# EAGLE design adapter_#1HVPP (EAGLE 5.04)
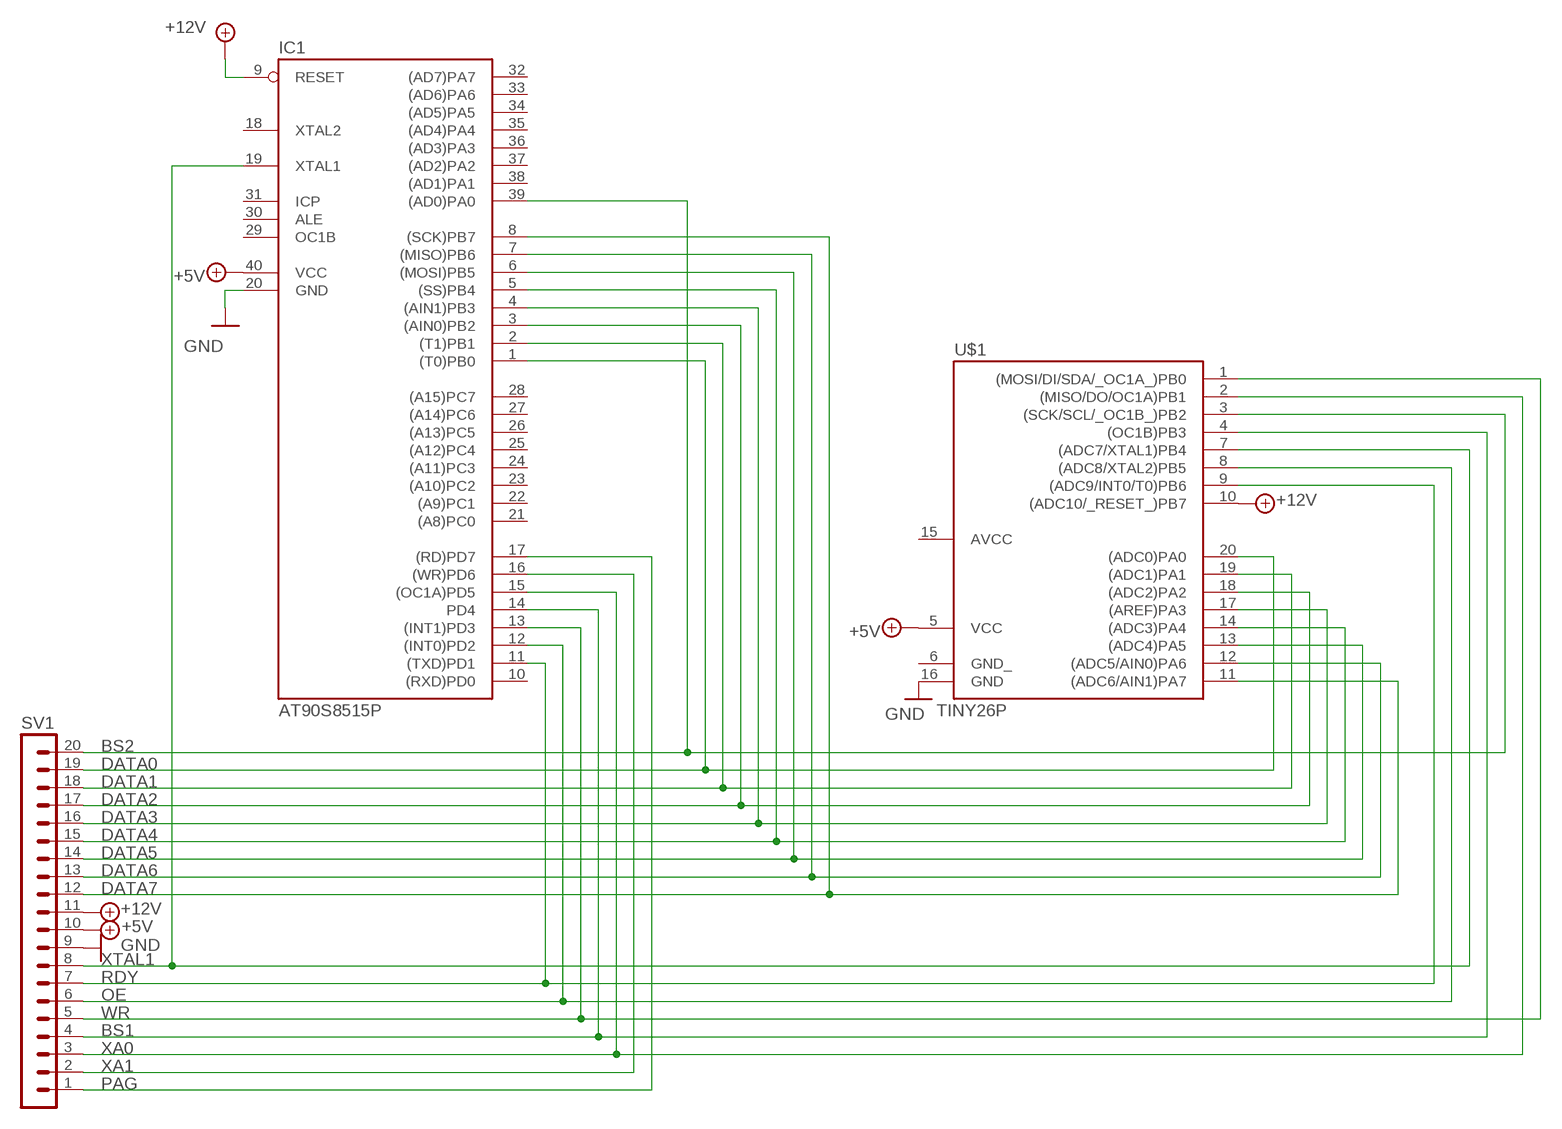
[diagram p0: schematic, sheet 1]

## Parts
IC1  AT90S8515P  [DIL40]
SV1  MA20-1  [MA20-1]
U$1  TINY26P  [DIL20]

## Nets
+5V: IC1.40(VCC) SV1.10 U$1.5(VCC)
+12V: IC1.9(RESET) SV1.11 U$1.10((ADC10/_RESET_)PB7)
BS1: IC1.14(PD4) SV1.4 U$1.4((OC1B)PB3)
BS2: IC1.39((AD0)PA0) SV1.20 U$1.3((SCK/SCL/_OC1B_)PB2)
DATA0: IC1.1((T0)PB0) SV1.19 U$1.20((ADC0)PA0)
DATA1: IC1.2((T1)PB1) SV1.18 U$1.19((ADC1)PA1)
DATA2: IC1.3((AIN0)PB2) SV1.17 U$1.18((ADC2)PA2)
DATA3: IC1.4((AIN1)PB3) SV1.16 U$1.17((AREF)PA3)
DATA4: IC1.5((SS)PB4) SV1.15 U$1.14((ADC3)PA4)
DATA5: IC1.6((MOSI)PB5) SV1.14 U$1.13((ADC4)PA5)
DATA6: IC1.7((MISO)PB6) SV1.13 U$1.12((ADC5/AIN0)PA6)
DATA7: IC1.8((SCK)PB7) SV1.12 U$1.11((ADC6/AIN1)PA7)
GND: IC1.20(GND) SV1.9 U$1.16(GND)
OE: IC1.12((INT0)PD2) SV1.6 U$1.8((ADC8/XTAL2)PB5)
PAG: IC1.17((RD)PD7) SV1.1
RDY: IC1.11((TXD)PD1) SV1.7 U$1.9((ADC9/INT0/T0)PB6)
WR: IC1.13((INT1)PD3) SV1.5 U$1.1((MOSI/DI/SDA/_OC1A_)PB0)
XA0: IC1.15((OC1A)PD5) SV1.3 U$1.2((MISO/DO/OC1A)PB1)
XA1: IC1.16((WR)PD6) SV1.2
XTAL1: IC1.19(XTAL1) SV1.8 U$1.7((ADC7/XTAL1)PB4)
Unconnected: IC1.10((RXD)PD0) IC1.18(XTAL2) IC1.21((A8)PC0) IC1.22((A9)PC1) IC1.23((A10)PC2) IC1.24((A11)PC3) IC1.25((A12)PC4) IC1.26((A13)PC5) IC1.27((A14)PC6) IC1.28((A15)PC7) IC1.29(OC1B) IC1.30(ALE) IC1.31(ICP) IC1.32((AD7)PA7) IC1.33((AD6)PA6) IC1.34((AD5)PA5) IC1.35((AD4)PA4) IC1.36((AD3)PA3) IC1.37((AD2)PA2) IC1.38((AD1)PA1)

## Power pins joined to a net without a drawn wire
AVCC: U$1.15(AVCC)
GND_: U$1.6(GND_)

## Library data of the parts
IC1 = avr-4:AT90S8515P: MICROCONTROLLER 8 Kbytes FLASH 512 bytes SRAM 512 bytes EEPROM UART
SV1 = con-lstb:MA20-1: PIN HEADER
U$1 = avr-4:TINY26

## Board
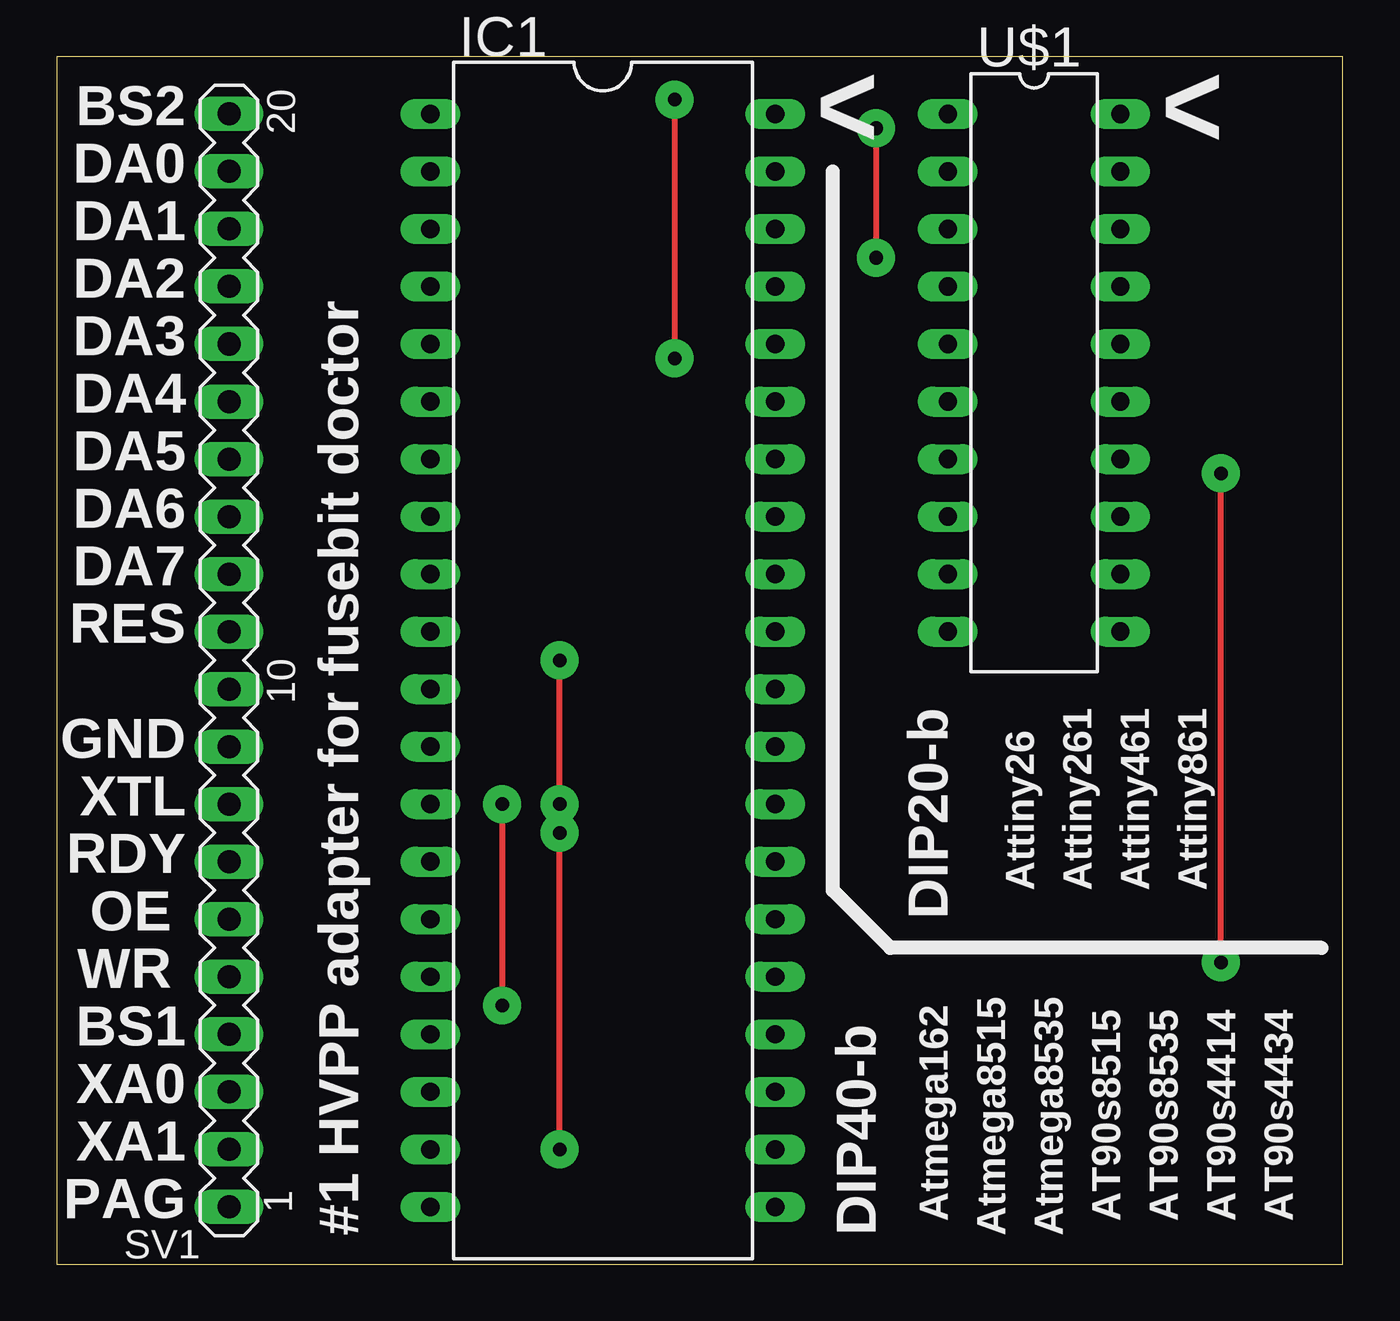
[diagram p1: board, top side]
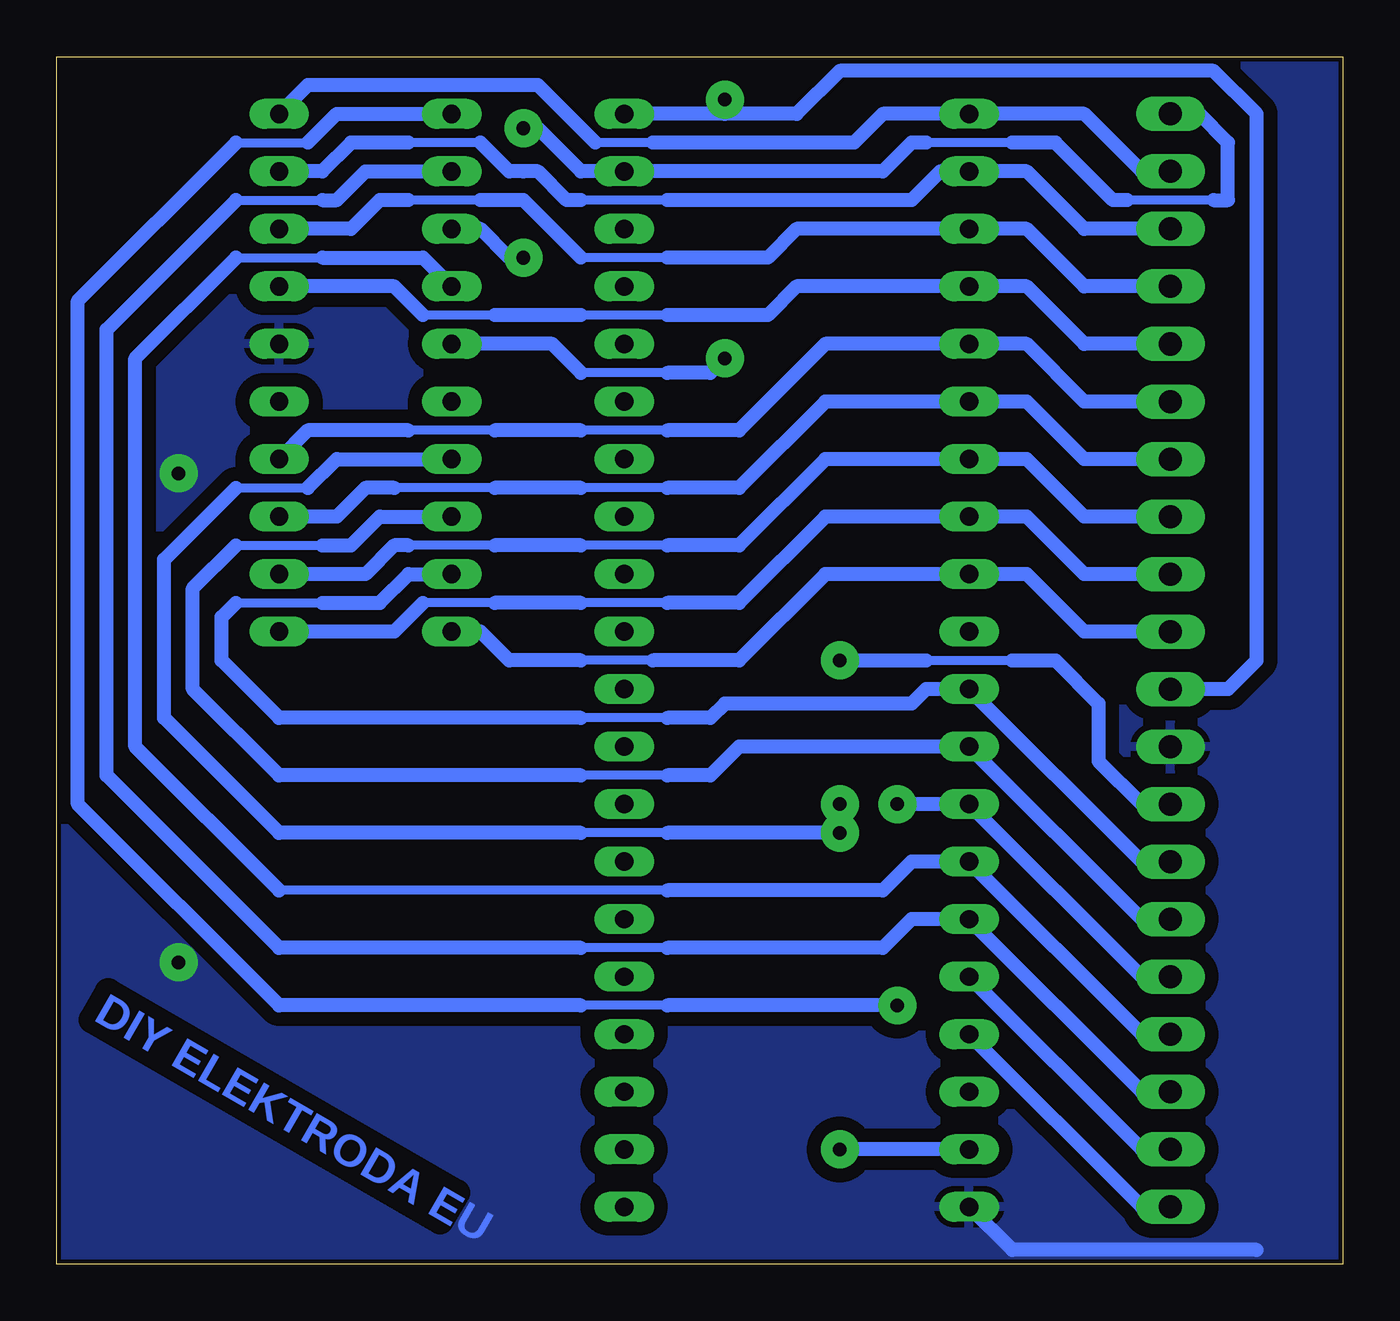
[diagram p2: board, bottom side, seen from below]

Size 56.82 x 53.33 mm. Coordinates in mm from the lower left corner, seen from the top.
Outline: 0,0 56.82,0 56.82,53.33 0,53.33 0,0
Copper layers (1*16): Top 0.035mm / dielectric 1.5mm / Bottom 0.035mm
Design rules "default *": minimum track width 10mil, minimum drill 24mil, track to track 24mil, track to pad 24mil, pad to pad 8mil, via to via 8mil, smd to smd 8mil, copper to edge 8mil, drill to drill 8mil, minimum pad ring 10mil, minimum via ring 8mil, stop-mask expansion 4mil, vias tented up to drill 0mil, thermal gap 10mil

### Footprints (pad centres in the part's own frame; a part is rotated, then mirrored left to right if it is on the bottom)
DIL40 = drill 0.813 long: 1 -24.13,-7.62; 2 -21.59,-7.62; 3 -19.05,-7.62; 4 -16.51,-7.62; 5 -13.97,-7.62; 6 -11.43,-7.62; 7 -8.89,-7.62; 8 -6.35,-7.62; 9 -3.81,-7.62; 10 -1.27,-7.62; 11 1.27,-7.62; 12 3.81,-7.62; 13 6.35,-7.62; 14 8.89,-7.62; 15 11.43,-7.62; 16 13.97,-7.62; 17 16.51,-7.62; 18 19.05,-7.62; 19 21.59,-7.62; 20 24.13,-7.62; 21 24.13,7.62; 22 21.59,7.62; 23 19.05,7.62; 24 16.51,7.62; 25 13.97,7.62; 26 11.43,7.62; 27 8.89,7.62; 28 6.35,7.62; 29 3.81,7.62; 30 1.27,7.62; 31 -1.27,7.62; 32 -3.81,7.62; 33 -6.35,7.62; 34 -8.89,7.62; 35 -11.43,7.62; 36 -13.97,7.62; 37 -16.51,7.62; 38 -19.05,7.62; 39 -21.59,7.62; 40 -24.13,7.62
MA20-1 = drill 1.016 long: 1 -24.13,0; 2 -21.59,0; 3 -19.05,0; 4 -16.51,0; 5 -13.97,0; 6 -11.43,0; 7 -8.89,0; 8 -6.35,0; 9 -3.81,0; 10 -1.27,0; 11 1.27,0; 12 3.81,0; 13 6.35,0; 14 8.89,0; 15 11.43,0; 16 13.97,0; 17 16.51,0; 18 19.05,0; 19 21.59,0; 20 24.13,0
DIL20 = drill 0.813 long: 1 -11.43,-3.81; 2 -8.89,-3.81; 3 -6.35,-3.81; 4 -3.81,-3.81; 5 -1.27,-3.81; 6 1.27,-3.81; 7 3.81,-3.81; 8 6.35,-3.81; 9 8.89,-3.81; 10 11.43,-3.81; 11 11.43,3.81; 12 8.89,3.81; 13 6.35,3.81; 14 3.81,3.81; 15 1.27,3.81; 16 -1.27,3.81; 17 -3.81,3.81; 18 -6.35,3.81; 19 -8.89,3.81; 20 -11.43,3.81

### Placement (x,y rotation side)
IC1  24.13,26.67 270 top
SV1  7.62,26.67 90 top
U$1  43.18,39.37 270 top

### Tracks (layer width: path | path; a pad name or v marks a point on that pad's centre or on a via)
+5V  (via drill 0.6 pad 1.68)
  Top 0.254: v27.3,51.44 v27.3,40.01
  Bottom 0.406: 29.84,39.37 33.66,39.37
  Bottom 0.61: SV1.10 5.08,25.4 3.81,26.67 3.81,50.8 5.71,52.7 22.23,52.7 24.13,50.8 27.3,50.8 | 27.3,50.8 IC1.40 | 27.3,50.8 v27.3,51.44 | U$1.5 34.92,40.64 33.66,39.37 | 29.84,39.37 27.94,39.37 v27.3,40.01
+12V
  Bottom 0.406: 30.48,26.67 33.66,26.67
  Bottom 0.61: SV1.11 11.43,27.94 13.97,30.48 IC1.9 22.86,30.48 26.67,26.67 30.48,26.67 | 33.66,26.67 36.83,26.67 38.1,27.94 U$1.10
BS1
  Bottom 0.406: 48.9,44.45 45.09,44.45 | 29.84,16.51 46.99,16.51
  Bottom 0.61: SV1.4 8.89,10.16 IC1.14 19.05,17.78 20.32,16.51 29.84,16.51 | U$1.4 40.64,44.45 45.09,44.45 | 48.9,44.45 53.34,40.01 53.34,22.86 46.99,16.51
BS2  (via drill 0.6 pad 1.68)
  Top 0.254: v36.2,50.16 v36.2,44.45
  Bottom 0.406: 5.71,46.99 9.53,46.99 | 14.61,49.53 18.41,49.53
  Bottom 0.61: SV1.20 6.35,50.8 5.08,49.53 5.08,46.99 5.71,46.99 | 9.53,46.99 10.16,46.99 12.7,49.53 14.61,49.53 | 18.41,49.53 19.05,49.53 20.32,48.26 IC1.39 33.66,48.26 35.56,50.16 v36.2,50.16 | U$1.3 38.1,45.72 36.83,44.45 v36.2,44.45
DATA0
  Bottom 0.406: 30.48,49.53 33.02,49.53
  Bottom 0.61: SV1.19 8.89,48.26 11.43,50.8 IC1.1 20.32,50.8 21.59,49.53 30.48,49.53 | 33.02,49.53 35.56,52.07 45.72,52.07 U$1.20
DATA1
  Bottom 0.406: 29.84,46.99 33.66,46.99 | 38.1,49.53 41.27,49.53
  Bottom 0.61: SV1.18 11.43,45.72 13.97,48.26 IC1.2 17.78,48.26 19.05,46.99 29.84,46.99 | 33.66,46.99 34.29,46.99 35.56,48.26 36.2,48.26 36.83,48.26 38.1,49.53 | 41.27,49.53 43.81,49.53 45.09,48.26 U$1.19
DATA2
  Bottom 0.406: 29.84,44.45 33.66,44.45 | 38.1,46.99 41.27,46.99
  Bottom 0.61: SV1.17 11.43,43.18 13.97,45.72 IC1.3 24.13,45.72 25.4,44.45 29.84,44.45 | 33.66,44.45 36.2,46.99 38.1,46.99 | 41.27,46.99 42.55,46.99 43.81,45.72 U$1.18
DATA3
  Bottom 0.406: 29.84,41.91 33.66,41.91 | 37.47,41.91 40.64,41.91
  Bottom 0.61: SV1.16 11.43,40.64 13.97,43.18 IC1.4 24.13,43.18 25.4,41.91 29.84,41.91 | 40.64,41.91 41.91,43.18 U$1.17 | 33.66,41.91 37.47,41.91
DATA4
  Bottom 0.406: 29.84,36.83 33.66,36.83 | 37.47,36.83 41.27,36.83
  Bottom 0.61: SV1.15 11.43,38.1 13.97,40.64 IC1.5 22.86,40.64 26.67,36.83 29.84,36.83 | 41.27,36.83 45.72,36.83 U$1.14 | 33.66,36.83 37.47,36.83
DATA5
  Bottom 0.406: 29.84,34.29 33.66,34.29 | 37.47,34.29 41.91,34.29
  Bottom 0.61: SV1.14 11.43,35.56 13.97,38.1 IC1.6 22.86,38.1 26.67,34.29 29.84,34.29 | 41.91,34.29 43.18,34.29 44.45,33.02 U$1.13 | 33.66,34.29 37.47,34.29
DATA6
  Bottom 0.406: 29.84,31.75 33.66,31.75 | 37.47,31.75 41.27,31.75
  Bottom 0.61: SV1.13 11.43,33.02 13.97,35.56 IC1.7 22.86,35.56 26.67,31.75 29.84,31.75 | 41.27,31.75 41.91,31.75 43.18,30.48 U$1.12 | 33.66,31.75 37.47,31.75
DATA7
  Bottom 0.406: 29.84,29.21 33.66,29.21 | 37.47,29.21 40.64,29.21
  Bottom 0.61: SV1.12 11.43,30.48 13.97,33.02 IC1.8 22.86,33.02 26.67,29.21 29.84,29.21 | 40.64,29.21 41.91,27.94 U$1.11 | 33.66,29.21 37.47,29.21
GND  (via drill 0.6 pad 1.68)
  Top 0.254: v51.44,13.34 v51.44,34.92
  Bottom 0.61: IC1.20 14.61,0.64 3.81,0.64
  pour Bottom: 0,53.34 56.52,53.34 56.52,0 0,0
OE
  Bottom 0.406: 48.9,31.75 45.09,31.75 | 29.84,21.59 33.66,21.59
  Bottom 0.61: SV1.6 8.89,15.24 IC1.12 26.67,22.86 27.94,21.59 29.84,21.59 | U$1.8 42.55,33.02 43.81,31.75 45.09,31.75 | 48.9,31.75 50.8,29.84 50.8,25.4 46.99,21.59 33.66,21.59
PAG
  Bottom 0.61: SV1.1 8.89,2.54 IC1.17
RDY
  Bottom 0.406: 48.9,29.21 45.09,29.21 | 29.84,24.13 33.66,24.13
  Bottom 0.61: SV1.7 8.89,17.78 IC1.11 18.41,25.4 19.05,24.77 27.3,24.77 27.94,24.13 29.84,24.13 | U$1.9 41.27,30.48 42.55,29.21 45.09,29.21 | 48.9,29.21 49.53,28.57 49.53,26.67 46.99,24.13 33.66,24.13
WR  (via drill 0.6 pad 1.68)
  Top 0.254: v19.68,20.32 v19.68,11.43
  Bottom 0.406: 48.9,49.53 45.72,49.53 | 29.84,11.43 33.66,11.43
  Bottom 0.61: SV1.5 8.89,12.7 IC1.13 v19.68,20.32 | U$1.1 44.45,50.8 45.72,49.53 | 48.9,49.53 55.88,42.55 55.88,20.32 46.99,11.43 33.66,11.43 | v19.68,11.43 29.84,11.43
XA0
  Bottom 0.406: 48.9,46.99 45.09,46.99 | 29.84,13.97 33.66,13.97
  Bottom 0.61: SV1.3 8.89,7.62 IC1.15 19.05,15.24 20.32,13.97 29.84,13.97 | U$1.2 43.18,48.26 44.45,46.99 45.09,46.99 | 48.9,46.99 54.61,41.27 54.61,21.59 46.99,13.97 33.66,13.97
XA1
  Bottom 0.61: SV1.2 8.89,5.08 IC1.16
XTAL1  (via drill 0.6 pad 1.68)
  Top 0.254: v22.23,5.08 v22.23,19.05 v22.23,20.32 v22.23,26.67
  Bottom 0.406: 18.41,26.67 14.61,26.67 | 48.9,34.29 45.72,34.29 | 29.84,19.05 33.66,19.05
  Bottom 0.61: SV1.8 8.89,20.32 10.79,22.23 10.79,24.77 12.7,26.67 14.61,26.67 | v22.23,26.67 18.41,26.67 | IC1.19 v22.23,5.08 | U$1.7 44.45,35.56 45.72,34.29 | 48.9,34.29 52.07,31.11 52.07,24.13 46.99,19.05 33.66,19.05 | v22.23,19.05 29.84,19.05

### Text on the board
Bottom: DIY ELEKTRODA EU
tPlace: BS2 | DA0 | ^ | ^ | DA1 | DA2 | DA3 | DA4 | DA5 | DA6 | DA7 | RES | GND | XTL | RDY | OE | Attiny26 | Attiny261 | Attiny461 | Attiny861 | DIP20-b | WR | BS1 | XA0 | XA1 | PAG | Atmega162 | AT90s8515 | AT90s8535 | AT90s4414 | AT90s4434 | #1 HVPP adapter for fusebit doctor | DIP40-b | Atmega8515 | Atmega8535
